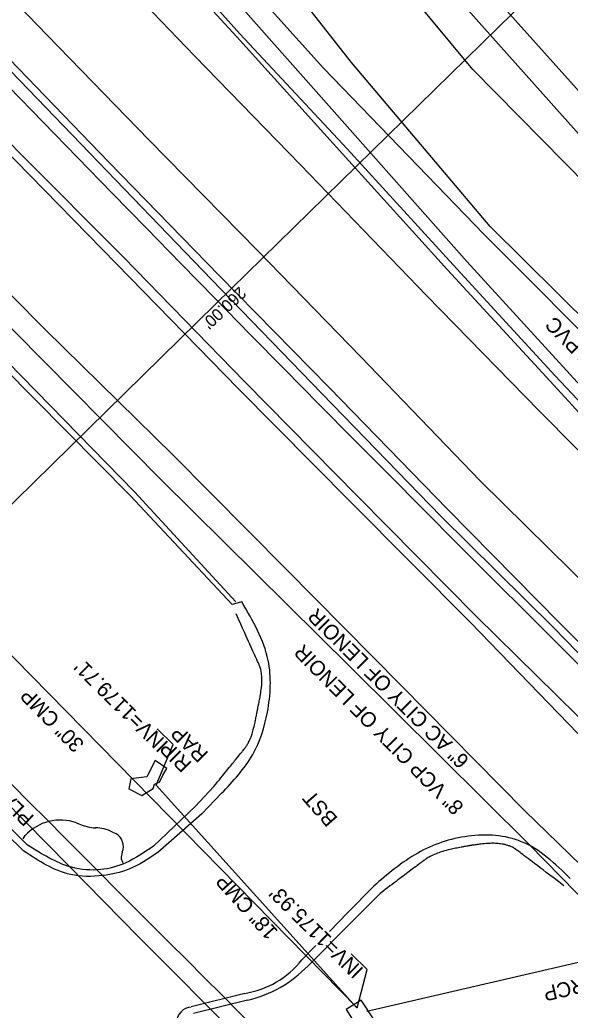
# Model space of a CAD drawing. Extents: x 1263837 to 1268319, y 770628 to 773628.
# Drawn here: x 1266860.6 to 1267007.9, y 771843 to 772108 of the extents above; entities that cross this region are included whole.
import ezdxf

# ---------------------------------------------------------------- set-up
doc = ezdxf.new("R2010")
doc.units = 0
for name, color, linetype in [('Exist Other Culture Area Outline', 7, 'Continuous'), ('Exist Other Culture Area Outline Text', 7, 'Continuous'), ('Exist Roads EOT Text', 7, 'Continuous'), ('Exist Structure Minor Catch Basin', 7, 'Continuous'), ('Exist Structure Minor Pipes CMP 30 Inch', 7, 'Continuous'), ('Exist Structure Minor Pipes CMP 30 Inch Leader', 7, 'Continuous'), ('Exist Structure Minor Pipes CMP 30 Inch Text', 7, 'Continuous'), ('Exist Utilities Gas UG Line SUE LOS B', 7, 'Continuous'), ('Exist Utilities Gas UG Line SUE LOS B Text', 7, 'Continuous'), ('Exist Utilities Telephone UG Cable SUE LOS B', 7, 'Continuous'), ('Exist Utilities Telephone UG FO SUE LOS B', 7, 'Continuous'), ('Exist Utilities Water UG Line SUE LOS B', 7, 'Continuous'), ('Exist Utilities Water UG Line SUE LOS B Text', 7, 'Continuous'), ('Prop Drainage Structure Pipe Alternate 42in Label', 7, 'Continuous'), ('Prop Drainage Structure Pipe RCP 18in Class III Label', 7, 'Continuous'), ('Prop Drainage Structure Pipe RCP 30in Class III Label', 7, 'Continuous'), ('Prop Drainage Structure Pipe RCP 42in Class III', 7, 'Continuous'), ('Prop Drainage Structure Pipe Welded Steel 60in Label', 7, 'Continuous'), ('Prop Drainage Structure Plot Symbol 20 Scale CELL', 7, 'Continuous'), ('Prop Drainage Structure Plot Symbol 50 Scale CELL', 7, 'Continuous'), ('Prop Horizontal Alignment', 7, 'Continuous'), ('Prop SS Fill Line', 7, 'Continuous'), ('Prop SS Fill Text', 7, 'Continuous'), ('Prop SS Transition Line', 7, 'Continuous'), ('Scratch_Level_0', 7, 'Continuous'), ('Scratch_Level_2', 7, 'Continuous'), ('Scratch_Level_5', 7, 'Continuous')]:
    doc.layers.add(name, color=color, linetype=linetype)

msp = doc.modelspace()

# ---------------------------------------------------------------- linework, layer by layer
at = {"layer": 'Exist Other Culture Area Outline'}
for p, q in [((1266875.8, 771893.09), (1266876.39, 771892.82)), ((1266880.3, 771891.77), (1266880.84, 771891.77)), ((1266861.5, 771888.83), (1266862.04, 771889.67)), ((1266885.41, 771890.63), (1266886.36, 771890.2)), ((1266888.04, 771885.26), (1266887.83, 771884.36)), ((1266888.12, 771882.63), (1266888.2, 771882.33))]:
    msp.add_line(p, q, dxfattribs=at)
msp.add_lwpolyline([(1266896.81, 771909.76), (1266894.59, 771905.39), (1266890.31, 771904.89), (1266889.76, 771902.18), (1266893.26, 771900.44), (1266896.34, 771902.24), (1266896.65, 771903.45), (1266898.05, 771904.02), (1266898.94, 771905.85), (1266899.98, 771907.6), (1266896.81, 771909.76)], dxfattribs=at)
for centre, major_axis, ratio, start_param, end_param in [((1266871.48, 771881.05), (-8.46, -9.6), 0.998994, 3.5195, 4.694413), ((1266882.63, 771908.56), (14.67, -8.71), 0.992625, 4.869418, 5.107673), ((1266880.74, 771881.65), (-3.34, 9.56), 0.998444, 5.467183, 5.937389), ((1266884.42, 771886.78), (2.35, 3.15), 0.998596, 4.955571, 6.407678), ((1266889.82, 771883.78), (-1.03, 1.83), 0.972951, 0.784815, 1.648672)]:
    msp.add_ellipse(centre, major_axis=major_axis, ratio=ratio, start_param=start_param, end_param=end_param, dxfattribs=at)
at = {"layer": 'Exist Structure Minor Catch Basin'}
msp.add_lwpolyline([(1266951.31, 771837.79), (1266955.42, 771840.41), (1266952, 771845.63), (1266947.98, 771843.16), (1266951.31, 771837.79)], dxfattribs=at)
at = {"layer": 'Exist Structure Minor Pipes CMP 30 Inch'}
msp.add_line((1266950.93, 771843.56), (1266810.43, 771986.77), dxfattribs=at)
at = {"layer": 'Exist Structure Minor Pipes CMP 30 Inch Leader'}
msp.add_lwpolyline([(1266950.93, 771843.56), (1266953.58, 771853.84), (1266949.31, 771858.06)], dxfattribs=at)
at = {"layer": 'Exist Utilities Gas UG Line SUE LOS B'}
for points in [[(1267251.66, 771778.25), (1267245.66, 771783.24), (1267207.76, 771821.81), (1267173.99, 771856.22), (1267107.23, 771924.68), (1267058.55, 771976.3), (1267021.45, 772013.9), (1266984.81, 772050.66), (1266941.85, 772095.07), (1266910.9, 772129.48), (1266882, 772160.62)], [(1266971.65, 771783.77), (1266957.01, 771797.69), (1266920.07, 771834.87), (1266892.49, 771862.5), (1266873.67, 771881.69), (1266844.74, 771910.96), (1266789.45, 771966.29), (1266767.15, 771988.48), (1266730.03, 772025.55), (1266701.19, 772053.36), (1266670.73, 772083.04), (1266635.53, 772115.83)]]:
    msp.add_lwpolyline(points, dxfattribs=at)
at = {"layer": 'Exist Utilities Telephone UG Cable SUE LOS B'}
for points in [[(1267045.29, 771973.62), (1267010.7, 772009.94), (1266980.19, 772043.3), (1266936.41, 772092.71), (1266907.08, 772125.97), (1266885.75, 772164.56), (1266881.04, 772182.11), (1266893.51, 772207.84), (1266893.04, 772220.24)], [(1267061.48, 771976.49), (1267022.89, 772016.68), (1266986.48, 772052.73), (1266949.35, 772096.59), (1266916.72, 772138.28), (1266892.38, 772169.77), (1266884.02, 772182.49), (1266894.19, 772207.62), (1266893.04, 772220.24)]]:
    msp.add_lwpolyline(points, dxfattribs=at)
at = {"layer": 'Exist Utilities Telephone UG FO SUE LOS B'}
for points in [[(1267063.99, 771976.99), (1267058.29, 772011.02), (1267043.56, 772028.46), (1267012.53, 772063.58), (1266981.88, 772094.72), (1266952.85, 772129.68), (1266918.67, 772160.32), (1266892.22, 772194.04), (1266869.77, 772217.7), (1266827.84, 772258.92), (1266816.85, 772269.34), (1266796.74, 772289.13)], [(1267109.33, 771998.14), (1267097.15, 772009.99), (1267062.43, 772037.02), (1267036.69, 772059.77), (1267011.11, 772087.97), (1266968.47, 772135.55), (1266950.56, 772163.04), (1266928.64, 772189.36), (1266913.94, 772213.45), (1266904.16, 772218.55)]]:
    msp.add_lwpolyline(points, dxfattribs=at)
at = {"layer": 'Exist Utilities Water UG Line SUE LOS B'}
msp.add_lwpolyline([(1267072.67, 771810.42), (1267034.8, 771848.56), (1266996.95, 771887.31), (1266949.11, 771934.79), (1266898.41, 771984.89), (1266859.29, 772024.49), (1266813.65, 772072.55)], dxfattribs=at)
at = {"layer": 'Prop Drainage Structure Pipe Alternate 42in Label'}
for p in [(1267006.59, 772123.63), (1266820.91, 771941.63)]:
    msp.add_line(p, (1266912.98, 772031.87), dxfattribs=at)
at = {"layer": 'Prop Drainage Structure Pipe RCP 18in Class III Label'}
msp.add_line((1267165.43, 771891.84), (1266953.49, 771842.57), dxfattribs=at)
at = {"layer": 'Prop Drainage Structure Pipe RCP 42in Class III'}
msp.add_line((1266950.83, 771843.62), (1266897.09, 771903.18), dxfattribs=at)
at = {"layer": 'Prop Drainage Structure Plot Symbol 50 Scale CELL'}
msp.add_lwpolyline([(1266897.09, 771903.18), (1266901.68, 771914.05), (1266897.41, 771918.27)], dxfattribs=at)
at = {"layer": 'Prop Horizontal Alignment'}
for radius, start in [(11329.16, 223.613619), (11589.16, 223.339648)]:
    msp.add_arc((1275094.23, 780056.99), radius, start, 225.433333, dxfattribs=at)
at = {"layer": 'Prop SS Fill Line'}
for p, q in [((1266907.51, 771897.44), (1266912.57, 771902.79)), ((1266907.51, 771897.44), (1266896.43, 771886.89)), ((1266957.01, 771874.21), (1266950.22, 771867.35)), ((1266950.22, 771867.35), (1266937.74, 771854.82)), ((1266921.56, 771845.61), (1266907.1, 771842.08))]:
    msp.add_line(p, q, dxfattribs=at)
msp.add_lwpolyline([(1266862.63, 771887.22), (1266838.66, 771910.83), (1266814, 771935.8), (1266786.64, 771963.14), (1266764.08, 771985.54), (1266738.65, 772009.54), (1266714.73, 772032.37), (1266698.83, 772047.56)], dxfattribs=at)
msp.add_ellipse((1266914.13, 771877.6), major_axis=(8.53, 31.72), ratio=0.998543, start_param=3.633515, end_param=4.20839, dxfattribs=at)
for points in [[(1266912.57, 771902.79), (1266913.98, 771904.54), (1266916.09, 771907.17), (1266918.56, 771910.23), (1266919.79, 771911.76), (1266920.41, 771912.53), (1266920.69, 771912.87), (1266920.79, 771913), (1266920.81, 771913.02), (1266920.82, 771913.04), (1266920.82, 771913.04), (1266920.85, 771913.07), (1266920.89, 771913.13), (1266920.94, 771913.19), (1266921.23, 771913.58), (1266921.47, 771913.94), (1266921.9, 771914.71), (1266922.1, 771915.12), (1266922.64, 771916.43), (1266922.94, 771917.4), (1266923.46, 771919.46), (1266923.68, 771920.55), (1266923.96, 771921.94), (1266924.01, 771922.22), (1266924.1, 771922.64), (1266924.13, 771922.78), (1266924.18, 771923.07), (1266924.21, 771923.21), (1266924.35, 771923.91), (1266924.47, 771924.46), (1266924.8, 771926.13), (1266925.01, 771927.24), (1266925.31, 771929.38), (1266925.4, 771930.41), (1266925.39, 771931.87), (1266925.37, 771932.34), (1266925.27, 771933.25), (1266925.2, 771933.68), (1266924.99, 771934.5), (1266924.87, 771934.9), (1266924.69, 771935.33), (1266924.66, 771935.38), (1266924.64, 771935.44), (1266924.63, 771935.46), (1266924.63, 771935.46), (1266924.62, 771935.48), (1266924.6, 771935.52), (1266924.52, 771935.69), (1266924.34, 771936.11), (1266922.31, 771940.59), (1266920.35, 771944.94), (1266918.5, 771949.04)], [(1267006.21, 771876.26), (1267002.27, 771879.24), (1266998.08, 771882.4), (1266993.83, 771885.61), (1266993.49, 771885.87), (1266993.39, 771885.94), (1266993.35, 771885.97), (1266993.34, 771885.98), (1266993.34, 771885.98), (1266993.33, 771885.99), (1266993.32, 771886), (1266993.22, 771886.07), (1266993.12, 771886.14), (1266992.67, 771886.44), (1266992.27, 771886.65), (1266991.42, 771887), (1266990.96, 771887.14), (1266989.98, 771887.37), (1266989.46, 771887.46), (1266987.83, 771887.63), (1266986.66, 771887.62), (1266984.25, 771887.46), (1266983.03, 771887.3), (1266981.7, 771887.09), (1266981.48, 771887.05), (1266981.26, 771887.02), (1266981.11, 771886.99), (1266981.04, 771886.98), (1266980.67, 771886.91), (1266980.37, 771886.86), (1266979.47, 771886.71), (1266978.87, 771886.6), (1266977.09, 771886.26), (1266975.91, 771886.01), (1266973.65, 771885.4), (1266972.57, 771885.04), (1266970.57, 771884.18), (1266969.65, 771883.67), (1266968.77, 771883.04), (1266968.71, 771883), (1266968.64, 771882.95), (1266968.62, 771882.93), (1266968.62, 771882.93), (1266968.6, 771882.92), (1266968.56, 771882.89), (1266968.4, 771882.77), (1266968, 771882.46), (1266967.13, 771881.81), (1266965.41, 771880.52), (1266961.95, 771877.92), (1266958.99, 771875.7), (1266957.01, 771874.21)]]:
    msp.add_open_spline(points, degree=3, dxfattribs=at)
msp.add_spline([(1266896.43, 771886.89), (1266888.96, 771882.39), (1266882.27, 771880.57), (1266874.51, 771881.21), (1266862.63, 771887.22)], degree=3, dxfattribs=at)
at = {"layer": 'Prop SS Fill Text'}
for p, q in [((1266909.31, 771895.48), (1266914.61, 771901)), ((1266909.31, 771895.48), (1266897.56, 771885.15)), ((1266955.32, 771876.16), (1266948.43, 771869.08)), ((1266948.43, 771869.08), (1266943.52, 771864.05)), ((1266939.82, 771860.25), (1266936.06, 771856.4)), ((1266920.87, 771847.45), (1266906.51, 771843.81))]:
    msp.add_line(p, q, dxfattribs=at)
for points in [[(1267107.62, 771824.41), (1267076.99, 771855.19), (1267044.88, 771886.99), (1267015.14, 771916.57), (1266982.81, 771948.3), (1266950.94, 771980.54), (1266920.8, 772011.08), (1266888.4, 772044.46), (1266861.03, 772071.99), (1266831.21, 772102.49), (1266811.7, 772122.46), (1266804.94, 772130.01), (1266809.19, 772134.56), (1266813.82, 772139.05), (1266823.78, 772129.93)], [(1266893.21, 772133.72), (1266919.52, 772104.22), (1266948.24, 772073.49), (1266976.6, 772042.43), (1267003.89, 772012.69), (1267030.51, 771984.42), (1267055.98, 771956.23), (1267082.18, 771926.96)], [(1267455.25, 771514.29), (1267427.43, 771541.62), (1267400.12, 771568.57), (1267372.32, 771596.01), (1267340.08, 771628.19), (1267310.1, 771656.99), (1267279.21, 771685.4), (1267248.96, 771712.93), (1267216.15, 771742.98), (1267185.9, 771770.94), (1267154.16, 771800.26), (1267123.77, 771828.98), (1267094.53, 771856.25), (1267062.43, 771886.08), (1267032.71, 771915.32), (1267003.31, 771945.43), (1266973.26, 771975.14), (1266941.46, 772007.96), (1266911.94, 772038.5), (1266853.53, 772099.1), (1266834.47, 772118.84), (1266823.63, 772130.08)], [(1266920.03, 771952.24), (1266917.45, 771951.57), (1266890.16, 771980.68), (1266856.13, 772015.1), (1266829.56, 772043.93), (1266805.4, 772080.75), (1266796.19, 772091.52)], [(1266861.69, 771885.52), (1266837.28, 771909.41), (1266812.64, 771934.41), (1266785.35, 771961.67), (1266762.88, 771983.98), (1266737.33, 772008.11), (1266713.27, 772030.96), (1266697.53, 772046.14), (1266696.19, 772047.61), (1266682.2, 772054.11), (1266681.56, 772053.48), (1266658.69, 772063.76)]]:
    msp.add_lwpolyline(points, dxfattribs=at)
for centre, major_axis, ratio, start_param, end_param in [((1266917.04, 771871.39), (4.6, 23.8), 0.998798, 3.491532, 4.236544), ((1266906.84, 771839.55), (-4.19, 0.81), 0.999299, 4.980055, 7.877567)]:
    msp.add_ellipse(centre, major_axis=major_axis, ratio=ratio, start_param=start_param, end_param=end_param, dxfattribs=at)
for points in [[(1266914.61, 771901), (1266922.94, 771911.35), (1266926.88, 771922.72), (1266927.09, 771936.58), (1266920.03, 771952.24)], [(1267007.89, 771878.21), (1266994.89, 771888.04), (1266980.56, 771889.51), (1266967.08, 771884.99), (1266955.32, 771876.16)], [(1266897.56, 771885.15), (1266889.78, 771880.67), (1266882.83, 771878.99), (1266874.23, 771879.27), (1266861.69, 771885.52)]]:
    msp.add_spline(points, degree=3, dxfattribs=at)
at = {"layer": 'Prop SS Transition Line'}
for points in [[(1266852.05, 772155.61), (1266878.43, 772128.6), (1266907.35, 772098.32), (1266935.74, 772069.18), (1266969.41, 772034.22), (1266999.55, 772003.34), (1267028.81, 771973.8), (1267057.41, 771945.22), (1267085.34, 771917.2), (1267106.93, 771895.42)], [(1267304.95, 771667.68), (1267283.19, 771688.65), (1267252.52, 771718.62), (1267221.74, 771748.68), (1267192.05, 771778.06), (1267161.19, 771808.07), (1267133.01, 771836.17), (1267104.3, 771864.66), (1267073.19, 771895.22), (1267043.99, 771924.5), (1267014.33, 771954.6), (1266983.78, 771984.63), (1266951.9, 772017.84), (1266924.19, 772046.24), (1266895.21, 772075.76), (1266867.96, 772103.92), (1266845.03, 772127.59), (1266834.72, 772138.35)], [(1266892.05, 772132.4), (1266918.74, 772103.45), (1266946.95, 772072.12), (1266975.02, 772041.09), (1267002.55, 772011.32), (1267028.69, 771982.73), (1267054.25, 771954.75), (1267080.46, 771925.43), (1267105.81, 771897.39), (1267132.71, 771869.91), (1267147, 771855.87), (1267172.96, 771830.15)], [(1267312.7, 771659.75), (1267281.75, 771687.98), (1267251.31, 771715.31), (1267218.37, 771745.12), (1267187.71, 771773.14), (1267155.87, 771802.24), (1267124.79, 771830.37), (1267095.52, 771857.21), (1267064.1, 771887.23), (1267034.38, 771917.11), (1267005.09, 771946.53), (1266975.1, 771977.02), (1266943.36, 772009.6), (1266914, 772039.61), (1266884.41, 772069.93), (1266855.32, 772100.03), (1266836.04, 772120.11), (1266825.49, 772131.16)], [(1267105.97, 771822.92), (1267075.27, 771852.97), (1267043.06, 771885.09), (1267012.57, 771914.24), (1266981.18, 771946.68), (1266949.21, 771978.94), (1266919.05, 772009.37), (1266886.5, 772042.74), (1266859.47, 772070.38), (1266829.65, 772101.27), (1266810.51, 772120.94)], [(1267058.33, 771834.45), (1267025.68, 771867.19), (1266995.72, 771896.29), (1266962.65, 771929.85), (1266931.79, 771961.07), (1266901.61, 771991.58), (1266867.53, 772025.04), (1266839.79, 772053), (1266809.46, 772083.06)], [(1266918.42, 771952.24), (1266891.29, 771981.67), (1266857.46, 772016.36)]]:
    msp.add_lwpolyline(points, dxfattribs=at)
at = {"layer": 'Scratch_Level_2'}
msp.add_arc((1275094.23, 780056.99), 11459.16, 216.983333, 225.433333, dxfattribs=at)
at = {"layer": 'Scratch_Level_5'}
msp.add_line((1266888.65, 772213.85), (1267056.62, 772025.19), dxfattribs=at)

# ---------------------------------------------------------------- texts
at = {"layer": 'Exist Other Culture Area Outline Text'}
for s, rotation, p in [('RAP', 135.3685, (1266911.31, 771911.73)), ('RIP', 135.3685, (1266906.88, 771909.08)), ('PLANTER', 135.4239, (1266864.71, 771894.69))]:
    msp.add_text(s, height=4, rotation=rotation, dxfattribs=at).set_placement(p)
at = {"layer": 'Exist Roads EOT Text'}
msp.add_text('BST', height=4, rotation=131.3556, dxfattribs=at).set_placement((1266945.89, 771894.31))
at = {"layer": 'Exist Structure Minor Pipes CMP 30 Inch Text'}
msp.add_text('30" CMP', height=4, rotation=134.4538, dxfattribs=at).set_placement((1266878.11, 771914.36))
at = {"layer": 'Exist Utilities Gas UG Line SUE LOS B Text'}
msp.add_text('4" PVC', height=4, rotation=134.9079, dxfattribs=at).set_placement((1267015.94, 772016.6))
at = {"layer": 'Exist Utilities Water UG Line SUE LOS B Text'}
msp.add_text('6" AC CITY OF LENOIR', height=4, rotation=135.2164, dxfattribs=at).set_placement((1266981.12, 771910.1))
at = {"layer": 'Prop Drainage Structure Pipe Alternate 42in Label'}
msp.add_text("260.00'", height=3.2, rotation=223.0448, dxfattribs=at).set_placement((1266919.36, 772036.78))
at = {"layer": 'Prop Drainage Structure Pipe RCP 30in Class III Label'}
msp.add_text('18" CMP', height=4, rotation=132.0646, dxfattribs=at).set_placement((1266929.92, 771864.06))
at = {"layer": 'Prop Drainage Structure Pipe Welded Steel 60in Label'}
msp.add_text('42" RCP', height=4, rotation=193.0876, dxfattribs=at).set_placement((1267020.49, 771853.84))
at = {"layer": 'Prop Drainage Structure Plot Symbol 20 Scale CELL'}
for s, p in [("INV=1179.71'", (1266900.64, 771914.45)), ("INV=1175.93'", (1266952.85, 771853.89))]:
    msp.add_text(s, height=4, rotation=135.3685, dxfattribs=at).set_placement(p)
at = {"layer": 'Scratch_Level_0'}
msp.add_text('8" VCP CITY OF LENOIR', height=4, rotation=134.7441, dxfattribs=at).set_placement((1266979.66, 771897.63))

doc.saveas('drawing.dxf')
